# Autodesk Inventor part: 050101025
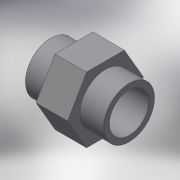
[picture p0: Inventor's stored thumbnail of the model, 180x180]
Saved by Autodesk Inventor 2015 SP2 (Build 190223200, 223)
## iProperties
Created: 2017-10
Part Number: 050101025
Material: Generic
Description: PLASSON THREADED SOCKET PVC 2.1/2"
Document SubType Name: Modeling
Designer: KIM
Density: 1 g/cm^3
Appearance: Default
Author: KIM
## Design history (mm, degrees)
derived "050101.ipt"
feature "Solid1::050101.ipt"
tag "TaggingFeature1"
body "Solid1"
other parameters: "d0" = 78, "d1" = 72.226, "d3" = 72.226, "d4" = 65.0034, "d5" = 29, "d6" = 29, "d7" = 86.6712, "d8" = 86.6712, "d10" = 20.3, "d13" = 0, "d14" = 0.72226, "G_" = 72.226, "lt_" = 29, "H_" = 78
